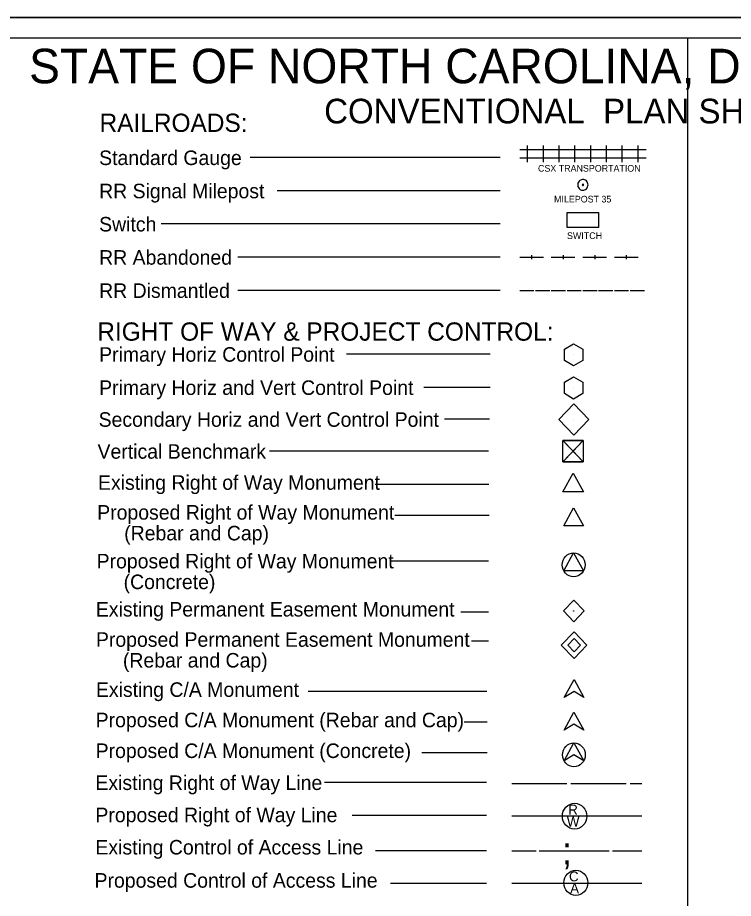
# Model space of a CAD drawing. Extents: x 2025847 to 2026166, y 840763 to 840870.
# Drawn here: x 2026057.38 to 2026094.71, y 840824.12 to 840870.09 of the extents above; entities that cross this region are included whole.
import ezdxf

# ---------------------------------------------------------------- set-up
doc = ezdxf.new("R2010")
doc.units = 0
for name, color, linetype in [('P_RDY_ROW_Permanent_Easement', 7, 'Continuous'), ('Sheet_Plan', 7, 'Continuous'), ('Sheet_Plot_Border_Outside_CELL', 7, 'Continuous'), ('Sheet_Symbology', 7, 'Continuous'), ('z - Construction', 7, 'Continuous')]:
    doc.layers.add(name, color=color, linetype=linetype)

msp = doc.modelspace()

# ---------------------------------------------------------------- linework, layer by layer
at = {"layer": 'P_RDY_ROW_Permanent_Easement'}
msp.add_line((2026086.401, 840837.34), (2026086.401, 840837.34), dxfattribs=at)
for points in [[(2026086.401, 840838.037), (2026087.064, 840837.34), (2026086.401, 840836.642), (2026085.738, 840837.34)], [(2026086.401, 840837.688), (2026086.733, 840837.34), (2026086.401, 840836.991), (2026086.07, 840837.34)]]:
    msp.add_lwpolyline(points, close=True, dxfattribs=at)
at = {"layer": 'Sheet_Plan'}
msp.add_line((2026164.548, 840869.009), (2026024.668, 840869.009), dxfattribs=at)
at = {"layer": 'Sheet_Plot_Border_Outside_CELL'}
msp.add_lwpolyline([(2026023.879, 840870.085), (2026165.546, 840870.085), (2026165.546, 840778.419), (2026023.879, 840778.419)], close=True, dxfattribs=at)
at = {"layer": 'Sheet_Symbology'}
for p, q in [((2026083.57, 840863.195), (2026084.393, 840863.195)), ((2026083.981, 840862.546), (2026083.981, 840863.412)), ((2026084.393, 840863.195), (2026085.216, 840863.195)), ((2026084.804, 840862.546), (2026084.804, 840863.412)), ((2026085.216, 840863.195), (2026086.039, 840863.195)), ((2026085.628, 840862.546), (2026085.628, 840863.412)), ((2026086.039, 840863.195), (2026086.862, 840863.195)), ((2026086.451, 840862.546), (2026086.451, 840863.412)), ((2026086.862, 840863.195), (2026087.685, 840863.195)), ((2026087.274, 840862.546), (2026087.274, 840863.412)), ((2026087.685, 840863.195), (2026088.509, 840863.195)), ((2026088.097, 840862.546), (2026088.097, 840863.412)), ((2026088.509, 840863.195), (2026089.332, 840863.195)), ((2026088.92, 840862.546), (2026088.92, 840863.412)), ((2026089.332, 840863.195), (2026090.155, 840863.195)), ((2026089.743, 840862.546), (2026089.743, 840863.412)), ((2026082.549, 840862.783), (2026069.509, 840862.783)), ((2026083.57, 840862.762), (2026084.393, 840862.762)), ((2026084.393, 840862.762), (2026085.216, 840862.762)), ((2026085.216, 840862.762), (2026086.039, 840862.762)), ((2026086.039, 840862.762), (2026086.862, 840862.762)), ((2026086.862, 840862.762), (2026087.685, 840862.762)), ((2026087.685, 840862.762), (2026088.509, 840862.762)), ((2026088.509, 840862.762), (2026089.332, 840862.762)), ((2026089.332, 840862.762), (2026090.155, 840862.762)), ((2026082.549, 840861.05), (2026070.92, 840861.05)), ((2026082.549, 840859.317), (2026064.859, 840859.317)), ((2026082.549, 840857.584), (2026068.872, 840857.584)), ((2026083.57, 840857.584), (2026084.804, 840857.584)), ((2026084.187, 840857.692), (2026084.187, 840857.475)), ((2026085.216, 840857.584), (2026086.451, 840857.584)), ((2026085.833, 840857.692), (2026085.833, 840857.475)), ((2026086.862, 840857.584), (2026088.097, 840857.584)), ((2026087.48, 840857.692), (2026087.48, 840857.475)), ((2026088.509, 840857.584), (2026089.743, 840857.584)), ((2026089.126, 840857.692), (2026089.126, 840857.475)), ((2026082.549, 840855.851), (2026068.872, 840855.851)), ((2026082.549, 840855.851), (2026068.872, 840855.851)), ((2026083.57, 840855.851), (2026084.31, 840855.851)), ((2026084.393, 840855.851), (2026085.134, 840855.851)), ((2026085.216, 840855.851), (2026085.957, 840855.851)), ((2026086.039, 840855.851), (2026086.78, 840855.851)), ((2026086.862, 840855.851), (2026087.603, 840855.851)), ((2026087.685, 840855.851), (2026088.426, 840855.851)), ((2026088.509, 840855.851), (2026089.249, 840855.851)), ((2026089.332, 840855.851), (2026090.073, 840855.851)), ((2026082.022, 840852.524), (2026074.529, 840852.524)), ((2026086.379, 840852.492), (2026086.379, 840852.492)), ((2026082.022, 840850.791), (2026078.571, 840850.791)), ((2026086.378, 840850.762), (2026086.378, 840850.762)), ((2026081.996, 840849.127), (2026079.646, 840849.127)), ((2026086.39, 840849.109), (2026086.39, 840849.109)), ((2026081.939, 840847.462), (2026070.51, 840847.462)), ((2026086.348, 840847.463), (2026086.348, 840847.463)), ((2026081.965, 840845.73), (2026076.034, 840845.73)), ((2026081.973, 840844.103), (2026077.056, 840844.103)), ((2026086.379, 840843.876), (2026086.379, 840843.876)), ((2026081.932, 840841.728), (2026076.871, 840841.728)), ((2026086.38, 840841.531), (2026086.38, 840841.531)), ((2026086.386, 840839.125), (2026086.386, 840839.125)), ((2026081.938, 840839.068), (2026080.494, 840839.068)), ((2026081.938, 840837.542), (2026081.049, 840837.542)), ((2026085.885, 840834.604), (2026086.4, 840835.539)), ((2026086.4, 840835.539), (2026086.914, 840834.604)), ((2026081.857, 840834.923), (2026072.535, 840834.923)), ((2026086.4, 840834.916), (2026085.885, 840834.604)), ((2026086.914, 840834.604), (2026086.4, 840834.916)), ((2026085.883, 840832.904), (2026086.397, 840833.84)), ((2026086.397, 840833.84), (2026086.912, 840832.904)), ((2026081.865, 840833.317), (2026080.666, 840833.317)), ((2026086.397, 840833.216), (2026085.883, 840832.904)), ((2026086.912, 840832.904), (2026086.397, 840833.216)), ((2026085.883, 840831.301), (2026086.397, 840832.236)), ((2026086.397, 840832.236), (2026086.912, 840831.301)), ((2026081.865, 840831.714), (2026078.457, 840831.714)), ((2026086.397, 840831.613), (2026085.883, 840831.301)), ((2026086.912, 840831.301), (2026086.397, 840831.613)), ((2026081.829, 840830.173), (2026073.39, 840830.173)), ((2026083.148, 840830.123), (2026086.029, 840830.123)), ((2026086.235, 840830.123), (2026089.116, 840830.123)), ((2026089.322, 840830.123), (2026089.939, 840830.123)), ((2026081.829, 840828.44), (2026074.828, 840828.44)), ((2026083.148, 840828.429), (2026089.939, 840828.429)), ((2026081.829, 840826.61), (2026076.047, 840826.61)), ((2026083.148, 840826.61), (2026084.421, 840826.61)), ((2026084.586, 840826.61), (2026088.242, 840826.61)), ((2026088.406, 840826.61), (2026089.939, 840826.61)), ((2026081.829, 840824.893), (2026076.831, 840824.893)), ((2026083.148, 840824.926), (2026089.939, 840824.926))]:
    msp.add_line(p, q, dxfattribs=at)
for points in [[(2026087.131, 840861.358), (2026087.125, 840861.414), (2026087.109, 840861.471), (2026087.082, 840861.521), (2026087.045, 840861.561), (2026087.002, 840861.595), (2026086.954, 840861.623), (2026086.906, 840861.634), (2026086.847, 840861.64), (2026086.794, 840861.628), (2026086.746, 840861.611), (2026086.698, 840861.583), (2026086.66, 840861.544), (2026086.628, 840861.493), (2026086.607, 840861.443), (2026086.596, 840861.386), (2026086.596, 840861.33), (2026086.607, 840861.274), (2026086.628, 840861.223), (2026086.66, 840861.172), (2026086.698, 840861.133), (2026086.746, 840861.105), (2026086.794, 840861.088), (2026086.847, 840861.077), (2026086.906, 840861.082), (2026086.954, 840861.094), (2026087.002, 840861.122), (2026087.045, 840861.155), (2026087.082, 840861.195), (2026087.109, 840861.246), (2026087.125, 840861.302), (2026087.131, 840861.358)], [(2026086.874, 840861.392), (2026086.858, 840861.392), (2026086.842, 840861.381), (2026086.831, 840861.364), (2026086.837, 840861.347), (2026086.847, 840861.33), (2026086.863, 840861.324), (2026086.879, 840861.33), (2026086.89, 840861.341), (2026086.895, 840861.364), (2026086.89, 840861.381), (2026086.874, 840861.392)], [(2026086.379, 840851.915), (2026085.902, 840852.201), (2026085.902, 840852.777), (2026086.379, 840853.069), (2026086.856, 840852.783), (2026086.856, 840852.201), (2026086.379, 840851.915)], [(2026086.881, 840848.024), (2026085.814, 840846.9), (2026086.347, 840847.462), (2026086.881, 840846.9), (2026085.814, 840848.024)], [(2026086.347, 840847.462), (2026086.881, 840848.024), (2026085.814, 840848.024), (2026086.347, 840847.462)], [(2026086.347, 840847.462), (2026085.814, 840846.9), (2026086.881, 840846.9), (2026086.347, 840847.462)], [(2026085.822, 840845.344), (2026086.357, 840846.321), (2026086.891, 840845.344), (2026085.822, 840845.344)]]:
    msp.add_lwpolyline(points, dxfattribs=at)
for points in [[(2026086.039, 840859.92), (2026087.685, 840859.92), (2026087.685, 840859.132), (2026086.039, 840859.132)], [(2026085.898, 840851.054), (2026086.381, 840851.338), (2026086.864, 840851.058), (2026086.856, 840850.476), (2026086.374, 840850.181), (2026085.898, 840850.464)], [(2026085.615, 840849.112), (2026086.394, 840849.931), (2026087.173, 840849.11), (2026086.395, 840848.291)], [(2026085.814, 840848.024), (2026086.881, 840848.024), (2026086.881, 840846.9), (2026085.814, 840846.9)], [(2026085.864, 840843.564), (2026086.379, 840844.5), (2026086.893, 840843.564)], [(2026085.866, 840841.219), (2026086.38, 840842.155), (2026086.895, 840841.219)], [(2026085.852, 840839.125), (2026086.387, 840839.688), (2026086.921, 840839.125), (2026086.387, 840838.562)]]:
    msp.add_lwpolyline(points, close=True, dxfattribs=at)
for centre, major_axis in [((2026086.38, 840841.531), (0, 0.624)), ((2026086.386, 840839.125), (0, 0.0109)), ((2026086.397, 840831.613), (0, 0.624)), ((2026086.429, 840828.412), (0, 0.672)), ((2026086.494, 840824.935), (0, 0.657))]:
    msp.add_ellipse(centre, major_axis=major_axis, ratio=0.95, dxfattribs=at)
at = {"layer": 'z - Construction'}
for p, q in [((2026165.546, 840870.085), (2026023.879, 840870.085)), ((2026092.318, 840869.009), (2026092.316, 840780.981))]:
    msp.add_line(p, q, dxfattribs=at)

# ---------------------------------------------------------------- texts
at = {"layer": 'Sheet_Symbology'}
for s, height, p in [('STATE OF NORTH CAROLINA, DIVISION OF HIGHWAYS', 1.80351, (2026057.976, 840866.657)), ('CONVENTIONAL  PLAN SHEET SYMBOLS', 1.28822, (2026073.367, 840864.564)), ('RAILROADS:', 0.9531, (2026061.65, 840864.121)), ('Standard Gauge', 0.75818, (2026061.628, 840862.391)), ('CSX TRANSPORTATION', 0.34659, (2026084.521, 840862.048)), ('RR Signal Milepost', 0.75818, (2026061.628, 840860.658)), ('MILEPOST 35', 0.34659, (2026085.36, 840860.439)), ('Switch', 0.7582, (2026061.628, 840858.925)), ('SWITCH', 0.3466, (2026086.035, 840858.533)), ('RR Abandoned', 0.75818, (2026061.628, 840857.192)), ('RR Dismantled', 0.75818, (2026061.628, 840855.459)), ('RIGHT OF WAY & PROJECT CONTROL:', 0.95314, (2026061.534, 840853.227)), ('Primary Horiz Control Point', 0.75818, (2026061.628, 840852.13)), ('Primary Horiz and Vert Control Point', 0.75818, (2026061.628, 840850.397)), ('Secondary Horiz and Vert Control Point', 0.75818, (2026061.602, 840848.733)), ('Vertical Benchmark', 0.75818, (2026061.545, 840847.067)), ('Existing Right of Way Monument', 0.75818, (2026061.571, 840845.446)), ('Proposed Right of Way Monument', 0.75818, (2026061.528, 840843.888)), ('     (Rebar and Cap)', 0.75818, (2026061.528, 840842.805)), ('Proposed Right of Way Monument', 0.75818, (2026061.497, 840841.345)), ('     (Concrete)', 0.75818, (2026061.497, 840840.262)), ('Existing Permanent Easement Monument', 0.75818, (2026061.458, 840838.833)), ('Proposed Permanent Easement Monument', 0.75818, (2026061.461, 840837.253)), ('     (Rebar and Cap)', 0.75818, (2026061.461, 840836.17)), ('Existing C/A Monument', 0.75818, (2026061.463, 840834.639)), ('Proposed C/A Monument (Rebar and Cap)', 0.75818, (2026061.446, 840833.053)), ('Proposed C/A Monument (Concrete)', 0.75818, (2026061.446, 840831.449)), ('Existing Right of Way Line', 0.75818, (2026061.435, 840829.779)), ('R', 0.526, (2026086.094, 840828.491)), ('Proposed Right of Way Line', 0.75818, (2026061.435, 840828.1)), ('W', 0.526, (2026086.023, 840827.871)), ('Existing Control of Access Line', 0.75818, (2026061.435, 840826.414)), (';', 1.43, (2026085.765, 840825.9)), ('Proposed Control of Access Line', 0.75818, (2026061.39, 840824.682)), ('C', 0.515, (2026086.141, 840825.012)), ('A', 0.515, (2026086.2, 840824.394))]:
    msp.add_text(s, height=height, dxfattribs=at).set_placement(p)

doc.saveas('drawing.dxf')
